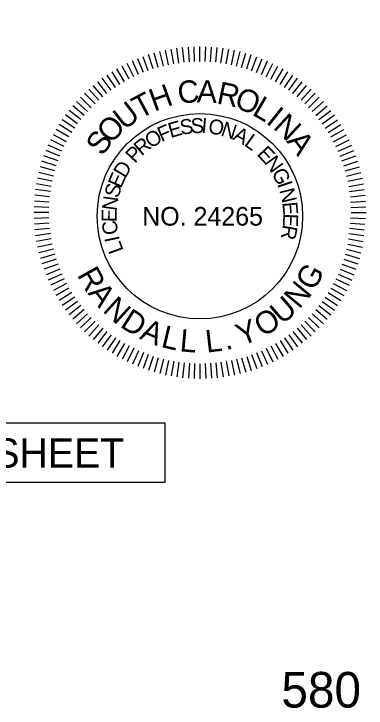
# Model space of a CAD drawing. Extents: x 1964850 to 1967424, y 1116563 to 1122204.
# Drawn here: x 1967339.7 to 1967423.6, y 1118175.5 to 1118341 of the extents above; entities that cross this region are included whole.
import ezdxf

# ---------------------------------------------------------------- set-up
doc = ezdxf.new("R2010")
doc.units = 0
for name, color, linetype in [('RD_DDB_Profile_Elev', 7, 'Continuous'), ('RD_SHT_MatchLine', 7, 'Continuous'), ('RD_Sketch1', 7, 'Continuous'), ('RD_TX_PEShield', 7, 'Continuous')]:
    doc.layers.add(name, color=color, linetype=linetype)

msp = doc.modelspace()

# ---------------------------------------------------------------- linework, layer by layer
at = {"layer": 'RD_Sketch1'}
msp.add_lwpolyline([(1967075.22, 1118243.5), (1967375.65, 1118243.5), (1967375.65, 1118229.24), (1967075.22, 1118229.24)], close=True, dxfattribs=at)
at = {"layer": 'RD_TX_PEShield'}
for p, q in [((1967375.29, 1118328.53), (1967374.43, 1118331.98)), ((1967375.29, 1118328.53), (1967374.43, 1118331.98)), ((1967376.5, 1118328.85), (1967375.76, 1118332.34)), ((1967376.5, 1118328.85), (1967375.76, 1118332.34)), ((1967377.75, 1118329.05), (1967377.13, 1118332.55)), ((1967377.75, 1118329.05), (1967377.13, 1118332.55)), ((1967378.99, 1118329.25), (1967378.49, 1118332.77)), ((1967378.99, 1118329.25), (1967378.49, 1118332.77)), ((1967380.23, 1118329.45), (1967379.86, 1118332.99)), ((1967380.23, 1118329.45), (1967379.86, 1118332.99)), ((1967381.49, 1118329.51), (1967381.24, 1118333.06)), ((1967381.49, 1118329.51), (1967381.24, 1118333.06)), ((1967382.74, 1118329.58), (1967382.62, 1118333.13)), ((1967382.74, 1118329.58), (1967382.62, 1118333.13)), ((1967384, 1118329.64), (1967384, 1118333.2)), ((1967384, 1118329.64), (1967384, 1118333.2)), ((1967385.25, 1118329.58), (1967385.38, 1118333.13)), ((1967385.25, 1118329.58), (1967385.38, 1118333.13)), ((1967386.51, 1118329.51), (1967386.76, 1118333.06)), ((1967386.51, 1118329.51), (1967386.76, 1118333.06)), ((1967387.77, 1118329.45), (1967388.14, 1118332.99)), ((1967387.77, 1118329.45), (1967388.14, 1118332.99)), ((1967389.01, 1118329.25), (1967389.5, 1118332.77)), ((1967389.01, 1118329.25), (1967389.5, 1118332.77)), ((1967390.25, 1118329.05), (1967390.87, 1118332.55)), ((1967390.25, 1118329.05), (1967390.87, 1118332.55)), ((1967391.49, 1118328.85), (1967392.23, 1118332.34)), ((1967391.49, 1118328.85), (1967392.23, 1118332.34)), ((1967391.49, 1118328.85), (1967392.23, 1118332.34)), ((1967392.71, 1118328.53), (1967393.57, 1118331.98)), ((1967392.71, 1118328.53), (1967393.57, 1118331.98)), ((1967392.71, 1118328.53), (1967393.57, 1118331.98)), ((1967370.51, 1118326.98), (1967369.18, 1118330.27)), ((1967370.51, 1118326.98), (1967369.18, 1118330.27)), ((1967371.68, 1118327.43), (1967370.47, 1118330.77)), ((1967371.68, 1118327.43), (1967370.47, 1118330.77)), ((1967372.86, 1118327.88), (1967371.76, 1118331.26)), ((1967372.86, 1118327.88), (1967371.76, 1118331.26)), ((1967374.07, 1118328.2), (1967373.09, 1118331.62)), ((1967374.07, 1118328.2), (1967373.09, 1118331.62)), ((1967393.92, 1118328.2), (1967394.9, 1118331.62)), ((1967393.92, 1118328.2), (1967394.9, 1118331.62)), ((1967393.92, 1118328.2), (1967394.9, 1118331.62)), ((1967395.14, 1118327.88), (1967396.24, 1118331.26)), ((1967395.14, 1118327.88), (1967396.24, 1118331.26)), ((1967395.14, 1118327.88), (1967396.24, 1118331.26)), ((1967396.31, 1118327.43), (1967397.53, 1118330.77)), ((1967396.31, 1118327.43), (1967397.53, 1118330.77)), ((1967396.31, 1118327.43), (1967397.53, 1118330.77)), ((1967397.48, 1118326.98), (1967398.82, 1118330.27)), ((1967397.48, 1118326.98), (1967398.82, 1118330.27)), ((1967397.48, 1118326.98), (1967398.82, 1118330.27)), ((1967367.1, 1118325.38), (1967365.43, 1118328.52)), ((1967367.1, 1118325.38), (1967365.43, 1118328.52)), ((1967368.22, 1118325.96), (1967366.66, 1118329.15)), ((1967368.22, 1118325.96), (1967366.66, 1118329.15)), ((1967369.34, 1118326.53), (1967367.89, 1118329.78)), ((1967369.34, 1118326.53), (1967367.89, 1118329.78)), ((1967398.66, 1118326.53), (1967400.11, 1118329.78)), ((1967398.66, 1118326.53), (1967400.11, 1118329.78)), ((1967398.66, 1118326.53), (1967400.11, 1118329.78)), ((1967399.78, 1118325.96), (1967401.34, 1118329.15)), ((1967399.78, 1118325.96), (1967401.34, 1118329.15)), ((1967399.78, 1118325.96), (1967401.34, 1118329.15)), ((1967400.9, 1118325.38), (1967402.57, 1118328.52)), ((1967400.9, 1118325.38), (1967402.57, 1118328.52)), ((1967400.9, 1118325.38), (1967402.57, 1118328.52)), ((1967364.92, 1118324.13), (1967363.04, 1118327.14)), ((1967364.92, 1118324.13), (1967363.04, 1118327.14)), ((1967365.98, 1118324.81), (1967364.2, 1118327.9)), ((1967365.98, 1118324.81), (1967364.2, 1118327.9)), ((1967402.02, 1118324.81), (1967403.8, 1118327.9)), ((1967402.02, 1118324.81), (1967403.8, 1118327.9)), ((1967402.02, 1118324.81), (1967403.8, 1118327.9)), ((1967403.08, 1118324.13), (1967404.96, 1118327.14)), ((1967403.08, 1118324.13), (1967404.96, 1118327.14)), ((1967403.08, 1118324.13), (1967404.96, 1118327.14)), ((1967362.81, 1118322.76), (1967360.72, 1118325.64)), ((1967362.81, 1118322.76), (1967360.72, 1118325.64)), ((1967363.87, 1118323.44), (1967361.88, 1118326.39)), ((1967363.87, 1118323.44), (1967361.88, 1118326.39)), ((1967404.13, 1118323.44), (1967406.12, 1118326.39)), ((1967404.13, 1118323.44), (1967406.12, 1118326.39)), ((1967404.13, 1118323.44), (1967406.12, 1118326.39)), ((1967405.18, 1118322.76), (1967407.28, 1118325.64)), ((1967405.18, 1118322.76), (1967407.28, 1118325.64)), ((1967405.18, 1118322.76), (1967407.28, 1118325.64)), ((1967360.86, 1118321.18), (1967358.57, 1118323.9)), ((1967360.86, 1118321.18), (1967358.57, 1118323.9)), ((1967361.83, 1118321.97), (1967359.64, 1118324.77)), ((1967361.83, 1118321.97), (1967359.64, 1118324.77)), ((1967406.16, 1118321.97), (1967408.35, 1118324.77)), ((1967406.16, 1118321.97), (1967408.35, 1118324.77)), ((1967406.16, 1118321.97), (1967408.35, 1118324.77)), ((1967407.14, 1118321.18), (1967409.42, 1118323.9)), ((1967407.14, 1118321.18), (1967409.42, 1118323.9)), ((1967407.14, 1118321.18), (1967409.42, 1118323.9)), ((1967358.99, 1118319.49), (1967356.52, 1118322.05)), ((1967358.99, 1118319.49), (1967356.52, 1118322.05)), ((1967359.88, 1118320.38), (1967357.5, 1118323.03)), ((1967359.88, 1118320.38), (1967357.5, 1118323.03)), ((1967408.12, 1118320.38), (1967410.5, 1118323.03)), ((1967408.12, 1118320.38), (1967410.5, 1118323.03)), ((1967408.12, 1118320.38), (1967410.5, 1118323.03)), ((1967409.01, 1118319.49), (1967411.48, 1118322.05)), ((1967409.01, 1118319.49), (1967411.48, 1118322.05)), ((1967409.01, 1118319.49), (1967411.48, 1118322.05)), ((1967358.1, 1118318.61), (1967355.54, 1118321.08)), ((1967358.1, 1118318.61), (1967355.54, 1118321.08)), ((1967409.89, 1118318.61), (1967412.45, 1118321.08)), ((1967409.89, 1118318.61), (1967412.45, 1118321.08)), ((1967409.89, 1118318.61), (1967412.45, 1118321.08)), ((1967356.42, 1118316.74), (1967353.7, 1118319.02)), ((1967356.42, 1118316.74), (1967353.7, 1118319.02)), ((1967357.21, 1118317.72), (1967354.57, 1118320.1)), ((1967357.21, 1118317.72), (1967354.57, 1118320.1)), ((1967410.78, 1118317.72), (1967413.43, 1118320.1)), ((1967410.78, 1118317.72), (1967413.43, 1118320.1)), ((1967410.78, 1118317.72), (1967413.43, 1118320.1)), ((1967411.58, 1118316.74), (1967414.3, 1118319.02)), ((1967411.58, 1118316.74), (1967414.3, 1118319.02)), ((1967411.58, 1118316.74), (1967414.3, 1118319.02)), ((1967354.84, 1118314.78), (1967351.96, 1118316.88)), ((1967354.84, 1118314.78), (1967351.96, 1118316.88)), ((1967355.63, 1118315.76), (1967352.83, 1118317.95)), ((1967355.63, 1118315.76), (1967352.83, 1118317.95)), ((1967412.37, 1118315.76), (1967415.17, 1118317.95)), ((1967412.37, 1118315.76), (1967415.17, 1118317.95)), ((1967412.37, 1118315.76), (1967415.17, 1118317.95)), ((1967413.16, 1118314.78), (1967416.04, 1118316.88)), ((1967413.16, 1118314.78), (1967416.04, 1118316.88)), ((1967413.16, 1118314.78), (1967416.04, 1118316.88)), ((1967354.15, 1118313.73), (1967351.2, 1118315.72)), ((1967354.15, 1118313.73), (1967351.2, 1118315.72)), ((1967413.84, 1118313.73), (1967416.79, 1118315.72)), ((1967413.84, 1118313.73), (1967416.79, 1118315.72)), ((1967413.84, 1118313.73), (1967416.79, 1118315.72)), ((1967353.47, 1118312.68), (1967350.45, 1118314.56)), ((1967353.47, 1118312.68), (1967350.45, 1118314.56)), ((1967414.53, 1118312.68), (1967417.54, 1118314.56)), ((1967414.53, 1118312.68), (1967417.54, 1118314.56)), ((1967414.53, 1118312.68), (1967417.54, 1118314.56)), ((1967352.21, 1118310.5), (1967349.07, 1118312.17)), ((1967352.21, 1118310.5), (1967349.07, 1118312.17)), ((1967352.78, 1118311.62), (1967349.7, 1118313.4)), ((1967352.78, 1118311.62), (1967349.7, 1118313.4)), ((1967415.21, 1118311.62), (1967418.3, 1118313.4)), ((1967415.21, 1118311.62), (1967418.3, 1118313.4)), ((1967415.21, 1118311.62), (1967418.3, 1118313.4)), ((1967415.78, 1118310.5), (1967418.92, 1118312.17)), ((1967415.78, 1118310.5), (1967418.92, 1118312.17)), ((1967415.78, 1118310.5), (1967418.92, 1118312.17)), ((1967351.64, 1118309.38), (1967348.44, 1118310.94)), ((1967351.64, 1118309.38), (1967348.44, 1118310.94)), ((1967416.36, 1118309.38), (1967419.55, 1118310.94)), ((1967416.36, 1118309.38), (1967419.55, 1118310.94)), ((1967416.36, 1118309.38), (1967419.55, 1118310.94)), ((1967351.07, 1118308.26), (1967347.82, 1118309.71)), ((1967351.07, 1118308.26), (1967347.82, 1118309.71)), ((1967416.93, 1118308.26), (1967420.18, 1118309.71)), ((1967416.93, 1118308.26), (1967420.18, 1118309.71)), ((1967416.93, 1118308.26), (1967420.18, 1118309.71)), ((1967350.17, 1118305.91), (1967346.83, 1118307.13)), ((1967350.17, 1118305.91), (1967346.83, 1118307.13)), ((1967350.62, 1118307.08), (1967347.32, 1118308.42)), ((1967350.62, 1118307.08), (1967347.32, 1118308.42)), ((1967417.38, 1118307.08), (1967420.67, 1118308.42)), ((1967417.38, 1118307.08), (1967420.67, 1118308.42)), ((1967417.38, 1118307.08), (1967420.67, 1118308.42)), ((1967417.83, 1118305.91), (1967421.17, 1118307.13)), ((1967417.83, 1118305.91), (1967421.17, 1118307.13)), ((1967417.83, 1118305.91), (1967421.17, 1118307.13)), ((1967349.72, 1118304.74), (1967346.33, 1118305.84)), ((1967349.72, 1118304.74), (1967346.33, 1118305.84)), ((1967418.28, 1118304.74), (1967421.66, 1118305.84)), ((1967418.28, 1118304.74), (1967421.66, 1118305.84)), ((1967418.28, 1118304.74), (1967421.66, 1118305.84)), ((1967349.39, 1118303.52), (1967345.97, 1118304.5)), ((1967349.39, 1118303.52), (1967345.97, 1118304.5)), ((1967418.6, 1118303.52), (1967422.02, 1118304.5)), ((1967418.6, 1118303.52), (1967422.02, 1118304.5)), ((1967418.6, 1118303.52), (1967422.02, 1118304.5)), ((1967349.07, 1118302.31), (1967345.62, 1118303.17)), ((1967349.07, 1118302.31), (1967345.62, 1118303.17)), ((1967418.93, 1118302.31), (1967422.38, 1118303.17)), ((1967418.93, 1118302.31), (1967422.38, 1118303.17)), ((1967418.93, 1118302.31), (1967422.38, 1118303.17)), ((1967348.54, 1118299.85), (1967345.04, 1118300.47)), ((1967348.54, 1118299.85), (1967345.04, 1118300.47)), ((1967348.74, 1118301.09), (1967345.26, 1118301.83)), ((1967348.74, 1118301.09), (1967345.26, 1118301.83)), ((1967419.25, 1118301.09), (1967422.74, 1118301.83)), ((1967419.25, 1118301.09), (1967422.74, 1118301.83)), ((1967419.25, 1118301.09), (1967422.74, 1118301.83)), ((1967419.45, 1118299.85), (1967422.95, 1118300.47)), ((1967419.45, 1118299.85), (1967422.95, 1118300.47)), ((1967419.45, 1118299.85), (1967422.95, 1118300.47)), ((1967348.35, 1118298.61), (1967344.83, 1118299.1)), ((1967348.35, 1118298.61), (1967344.83, 1118299.1)), ((1967419.65, 1118298.61), (1967423.17, 1118299.1)), ((1967419.65, 1118298.61), (1967423.17, 1118299.1)), ((1967419.65, 1118298.61), (1967423.17, 1118299.1)), ((1967348.15, 1118297.37), (1967344.61, 1118297.74)), ((1967348.15, 1118297.37), (1967344.61, 1118297.74)), ((1967419.85, 1118297.37), (1967423.39, 1118297.74)), ((1967419.85, 1118297.37), (1967423.39, 1118297.74)), ((1967419.85, 1118297.37), (1967423.39, 1118297.74)), ((1967348.08, 1118296.11), (1967344.54, 1118296.36)), ((1967348.08, 1118296.11), (1967344.54, 1118296.36)), ((1967419.91, 1118296.11), (1967423.46, 1118296.36)), ((1967419.91, 1118296.11), (1967423.46, 1118296.36)), ((1967419.91, 1118296.11), (1967423.46, 1118296.36)), ((1967348.02, 1118294.85), (1967344.46, 1118294.98)), ((1967348.02, 1118294.85), (1967344.46, 1118294.98)), ((1967419.98, 1118294.85), (1967423.53, 1118294.98)), ((1967419.98, 1118294.85), (1967423.53, 1118294.98)), ((1967419.98, 1118294.85), (1967423.53, 1118294.98)), ((1967347.95, 1118293.6), (1967344.39, 1118293.6)), ((1967347.95, 1118293.6), (1967344.39, 1118293.6)), ((1967348.02, 1118292.34), (1967344.46, 1118292.22)), ((1967348.02, 1118292.34), (1967344.46, 1118292.22)), ((1967419.91, 1118292.34), (1967423.46, 1118292.22)), ((1967419.91, 1118292.34), (1967423.46, 1118292.22)), ((1967420.04, 1118293.6), (1967423.6, 1118293.6)), ((1967420.04, 1118293.6), (1967423.6, 1118293.6)), ((1967420.04, 1118293.6), (1967423.6, 1118293.6)), ((1967348.08, 1118291.09), (1967344.54, 1118290.84)), ((1967348.08, 1118291.09), (1967344.54, 1118290.84)), ((1967419.78, 1118291.1), (1967423.31, 1118290.85)), ((1967419.78, 1118291.1), (1967423.31, 1118290.85)), ((1967348.15, 1118289.83), (1967344.61, 1118289.46)), ((1967348.15, 1118289.83), (1967344.61, 1118289.46)), ((1967419.65, 1118289.85), (1967423.17, 1118289.48)), ((1967419.65, 1118289.85), (1967423.17, 1118289.48)), ((1967348.35, 1118288.59), (1967344.83, 1118288.09)), ((1967348.35, 1118288.59), (1967344.83, 1118288.09)), ((1967348.54, 1118287.35), (1967345.04, 1118286.73)), ((1967348.54, 1118287.35), (1967345.04, 1118286.73)), ((1967419.39, 1118287.36), (1967422.88, 1118286.74)), ((1967419.39, 1118287.36), (1967422.88, 1118286.74)), ((1967419.52, 1118288.61), (1967423.03, 1118288.11)), ((1967419.52, 1118288.61), (1967423.03, 1118288.11)), ((1967348.74, 1118286.1), (1967345.26, 1118285.36)), ((1967348.74, 1118286.1), (1967345.26, 1118285.36)), ((1967419.25, 1118286.1), (1967422.74, 1118285.36)), ((1967419.25, 1118286.1), (1967422.74, 1118285.36)), ((1967349.07, 1118284.89), (1967345.62, 1118284.03)), ((1967349.07, 1118284.89), (1967345.62, 1118284.03)), ((1967418.93, 1118284.89), (1967422.38, 1118284.03)), ((1967418.93, 1118284.89), (1967422.38, 1118284.03)), ((1967349.39, 1118283.67), (1967345.97, 1118282.69)), ((1967349.39, 1118283.67), (1967345.97, 1118282.69)), ((1967349.72, 1118282.46), (1967346.33, 1118281.36)), ((1967418.28, 1118282.46), (1967421.66, 1118281.36)), ((1967418.28, 1118282.46), (1967421.66, 1118281.36)), ((1967418.6, 1118283.67), (1967422.02, 1118282.69)), ((1967418.6, 1118283.67), (1967422.02, 1118282.69)), ((1967350.17, 1118281.28), (1967346.83, 1118280.07)), ((1967350.17, 1118281.28), (1967346.83, 1118280.07)), ((1967417.83, 1118281.28), (1967421.17, 1118280.07)), ((1967417.83, 1118281.28), (1967421.17, 1118280.07)), ((1967350.62, 1118280.11), (1967347.32, 1118278.78)), ((1967350.62, 1118280.11), (1967347.32, 1118278.78)), ((1967351.07, 1118278.94), (1967347.82, 1118277.49)), ((1967351.07, 1118278.94), (1967347.82, 1118277.49)), ((1967416.93, 1118278.94), (1967420.18, 1118277.49)), ((1967416.93, 1118278.94), (1967420.18, 1118277.49)), ((1967417.38, 1118280.11), (1967420.67, 1118278.78)), ((1967417.38, 1118280.11), (1967420.67, 1118278.78)), ((1967351.64, 1118277.82), (1967348.44, 1118276.26)), ((1967351.64, 1118277.82), (1967348.44, 1118276.26)), ((1967416.36, 1118277.82), (1967419.55, 1118276.26)), ((1967416.36, 1118277.82), (1967419.55, 1118276.26)), ((1967352.21, 1118276.7), (1967349.07, 1118275.03)), ((1967352.21, 1118276.7), (1967349.07, 1118275.03)), ((1967352.78, 1118275.58), (1967349.7, 1118273.8)), ((1967352.78, 1118275.58), (1967349.7, 1118273.8)), ((1967415.21, 1118275.58), (1967418.3, 1118273.8)), ((1967415.21, 1118275.58), (1967418.3, 1118273.8)), ((1967415.78, 1118276.7), (1967418.92, 1118275.03)), ((1967415.78, 1118276.7), (1967418.92, 1118275.03)), ((1967353.47, 1118274.52), (1967350.45, 1118272.64)), ((1967353.47, 1118274.52), (1967350.45, 1118272.64)), ((1967414.53, 1118274.52), (1967417.54, 1118272.64)), ((1967414.53, 1118274.52), (1967417.54, 1118272.64)), ((1967354.15, 1118273.47), (1967351.2, 1118271.48)), ((1967354.15, 1118273.47), (1967351.2, 1118271.48)), ((1967354.84, 1118272.41), (1967351.96, 1118270.32)), ((1967354.84, 1118272.41), (1967351.96, 1118270.32)), ((1967413.16, 1118272.41), (1967416.04, 1118270.32)), ((1967413.16, 1118272.41), (1967416.04, 1118270.32)), ((1967413.84, 1118273.47), (1967416.79, 1118271.48)), ((1967413.84, 1118273.47), (1967416.79, 1118271.48)), ((1967355.63, 1118271.43), (1967352.83, 1118269.24)), ((1967355.63, 1118271.43), (1967352.83, 1118269.24)), ((1967412.37, 1118271.43), (1967415.17, 1118269.24)), ((1967412.37, 1118271.43), (1967415.17, 1118269.24)), ((1967356.42, 1118270.46), (1967353.7, 1118268.17)), ((1967356.42, 1118270.46), (1967353.7, 1118268.17)), ((1967357.21, 1118269.48), (1967354.57, 1118267.1)), ((1967357.21, 1118269.48), (1967354.57, 1118267.1)), ((1967410.78, 1118269.48), (1967413.43, 1118267.1)), ((1967410.78, 1118269.48), (1967413.43, 1118267.1)), ((1967411.58, 1118270.46), (1967414.3, 1118268.17)), ((1967411.58, 1118270.46), (1967414.3, 1118268.17)), ((1967358.1, 1118268.59), (1967355.54, 1118266.12)), ((1967358.1, 1118268.59), (1967355.54, 1118266.12)), ((1967358.99, 1118267.7), (1967356.52, 1118265.14)), ((1967358.99, 1118267.7), (1967356.52, 1118265.14)), ((1967409.01, 1118267.7), (1967411.48, 1118265.14)), ((1967409.01, 1118267.7), (1967411.48, 1118265.14)), ((1967409.89, 1118268.59), (1967412.45, 1118266.12)), ((1967409.89, 1118268.59), (1967412.45, 1118266.12)), ((1967359.88, 1118266.81), (1967357.5, 1118264.17)), ((1967359.88, 1118266.81), (1967357.5, 1118264.17)), ((1967360.86, 1118266.02), (1967358.57, 1118263.3)), ((1967360.86, 1118266.02), (1967358.57, 1118263.3)), ((1967407.14, 1118266.02), (1967409.42, 1118263.3)), ((1967407.14, 1118266.02), (1967409.42, 1118263.3)), ((1967408.12, 1118266.81), (1967410.5, 1118264.17)), ((1967361.83, 1118265.23), (1967359.64, 1118262.43)), ((1967361.83, 1118265.23), (1967359.64, 1118262.43)), ((1967362.81, 1118264.44), (1967360.72, 1118261.56)), ((1967362.81, 1118264.44), (1967360.72, 1118261.56)), ((1967405.18, 1118264.44), (1967407.28, 1118261.56)), ((1967405.18, 1118264.44), (1967407.28, 1118261.56)), ((1967406.16, 1118265.23), (1967408.35, 1118262.43)), ((1967406.16, 1118265.23), (1967408.35, 1118262.43)), ((1967363.87, 1118263.75), (1967361.88, 1118260.8)), ((1967363.87, 1118263.75), (1967361.88, 1118260.8)), ((1967364.92, 1118263.07), (1967363.04, 1118260.05)), ((1967364.92, 1118263.07), (1967363.04, 1118260.05)), ((1967365.98, 1118262.38), (1967364.2, 1118259.3)), ((1967365.98, 1118262.38), (1967364.2, 1118259.3)), ((1967402.02, 1118262.38), (1967403.8, 1118259.3)), ((1967402.02, 1118262.38), (1967403.8, 1118259.3)), ((1967403.08, 1118263.07), (1967404.96, 1118260.05)), ((1967403.08, 1118263.07), (1967404.96, 1118260.05)), ((1967404.13, 1118263.75), (1967406.12, 1118260.8)), ((1967404.13, 1118263.75), (1967406.12, 1118260.8)), ((1967367.1, 1118261.81), (1967365.43, 1118258.67)), ((1967367.1, 1118261.81), (1967365.43, 1118258.67)), ((1967368.22, 1118261.24), (1967366.66, 1118258.04)), ((1967368.22, 1118261.24), (1967366.66, 1118258.04)), ((1967369.34, 1118260.67), (1967367.89, 1118257.42)), ((1967369.34, 1118260.67), (1967367.89, 1118257.42)), ((1967398.66, 1118260.67), (1967400.11, 1118257.42)), ((1967398.66, 1118260.67), (1967400.11, 1118257.42)), ((1967399.78, 1118261.24), (1967401.34, 1118258.04)), ((1967399.78, 1118261.24), (1967401.34, 1118258.04)), ((1967400.9, 1118261.81), (1967402.57, 1118258.67)), ((1967400.9, 1118261.81), (1967402.57, 1118258.67)), ((1967370.51, 1118260.22), (1967369.18, 1118256.92)), ((1967370.51, 1118260.22), (1967369.18, 1118256.92)), ((1967371.68, 1118259.77), (1967370.47, 1118256.43)), ((1967371.68, 1118259.77), (1967370.47, 1118256.43)), ((1967372.86, 1118259.32), (1967371.76, 1118255.93)), ((1967372.86, 1118259.32), (1967371.76, 1118255.93)), ((1967374.07, 1118258.99), (1967373.09, 1118255.57)), ((1967374.07, 1118258.99), (1967373.09, 1118255.57)), ((1967393.92, 1118258.99), (1967394.9, 1118255.57)), ((1967393.92, 1118258.99), (1967394.9, 1118255.57)), ((1967395.14, 1118259.32), (1967396.24, 1118255.93)), ((1967395.14, 1118259.32), (1967396.24, 1118255.93)), ((1967396.31, 1118259.77), (1967397.53, 1118256.43)), ((1967396.31, 1118259.77), (1967397.53, 1118256.43)), ((1967397.48, 1118260.22), (1967398.82, 1118256.92)), ((1967397.48, 1118260.22), (1967398.82, 1118256.92)), ((1967375.29, 1118258.67), (1967374.43, 1118255.22)), ((1967375.29, 1118258.67), (1967374.43, 1118255.22)), ((1967376.5, 1118258.34), (1967375.76, 1118254.86)), ((1967376.5, 1118258.34), (1967375.76, 1118254.86)), ((1967377.75, 1118258.14), (1967377.13, 1118254.64)), ((1967377.75, 1118258.14), (1967377.13, 1118254.64)), ((1967378.99, 1118257.95), (1967378.49, 1118254.43)), ((1967378.99, 1118257.95), (1967378.49, 1118254.43)), ((1967380.23, 1118257.75), (1967379.86, 1118254.21)), ((1967380.23, 1118257.75), (1967379.86, 1118254.21)), ((1967381.49, 1118257.68), (1967381.24, 1118254.14)), ((1967381.49, 1118257.68), (1967381.24, 1118254.14)), ((1967382.74, 1118257.62), (1967382.62, 1118254.06)), ((1967382.74, 1118257.62), (1967382.62, 1118254.06)), ((1967384, 1118257.55), (1967384, 1118253.99)), ((1967384, 1118257.55), (1967384, 1118253.99)), ((1967385.25, 1118257.62), (1967385.38, 1118254.06)), ((1967385.25, 1118257.62), (1967385.38, 1118254.06)), ((1967386.51, 1118257.68), (1967386.76, 1118254.14)), ((1967386.51, 1118257.68), (1967386.76, 1118254.14)), ((1967387.77, 1118257.75), (1967388.14, 1118254.21)), ((1967387.77, 1118257.75), (1967388.14, 1118254.21)), ((1967389.01, 1118257.95), (1967389.5, 1118254.43)), ((1967389.01, 1118257.95), (1967389.5, 1118254.43)), ((1967390.25, 1118258.14), (1967390.87, 1118254.64)), ((1967390.25, 1118258.14), (1967390.87, 1118254.64)), ((1967391.49, 1118258.34), (1967392.23, 1118254.86)), ((1967391.49, 1118258.34), (1967392.23, 1118254.86)), ((1967392.71, 1118258.67), (1967393.57, 1118255.22)), ((1967392.71, 1118258.67), (1967393.57, 1118255.22))]:
    msp.add_line(p, q, dxfattribs=at)
msp.add_circle((1967384, 1118292.72), 24.48, dxfattribs=at)

# ---------------------------------------------------------------- texts
at = {"layer": 'RD_DDB_Profile_Elev'}
msp.add_text('580', height=8.5, dxfattribs=at).set_placement((1967403.42, 1118175.58))
at = {"layer": 'RD_SHT_MatchLine'}
msp.add_text('Match Line Sta. 70+00.00 (See Sheet No. 8)', height=8, rotation=77.0152, dxfattribs=at).set_placement((1967301.59, 1118288.26))
at = {"layer": 'RD_Sketch1'}
msp.add_text('ALIGNMENT CONTROL CAN BE FOUND ON REFERENCE SHEET', height=7, dxfattribs=at).set_placement((1967078.87, 1118232.79))
at = {"layer": 'RD_TX_PEShield'}
for s, height, rotation, p in [('C', 5.34, 6.8832, (1967378.99, 1118319.46)), ('A', 5.34, 357.9448, (1967383.21, 1118319.91)), ('H', 5.34, 19.9102, (1967373.09, 1118317.64)), ('R', 5.34, 348.267, (1967387.79, 1118319.66)), ('T', 5.34, 28.0947, (1967369.66, 1118315.83)), ('O', 5.34, 339.3286, (1967391.93, 1118318.74)), ('L', 5.34, 329.6507, (1967396.19, 1118317.04)), ('U', 5.34, 37.7726, (1967365.98, 1118313.09)), ('I', 5.34, 321.4663, (1967399.53, 1118315.05)), ('N', 5.34, 317.0007, (1967401.22, 1118313.78)), ('O', 5.34, 47.4504, (1967362.81, 1118309.78)), ('E', 3.56, 16.1843, (1967377, 1118311.35)), ('S', 3.56, 8.6909, (1967379.49, 1118312.11)), ('S', 3.56, 1.79, (1967381.85, 1118312.51)), ('I', 3.56, 354.889, (1967384.24, 1118312.62)), ('O', 3.56, 350.4045, (1967385.8, 1118312.54)), ('N', 3.56, 341.7029, (1967388.78, 1118312.04)), ('F', 3.56, 23.0853, (1967374.81, 1118310.38)), ('A', 3.56, 333.0013, (1967391.64, 1118311.1)), ('S', 5.34, 54.9027, (1967360.77, 1118306.88)), ('O', 3.56, 31.7869, (1967372.24, 1118308.78)), ('L', 3.56, 324.2997, (1967394.34, 1118309.73)), ('A', 5.34, 307.3229, (1967404.51, 1118310.58)), ('R', 3.56, 39.8902, (1967370.09, 1118306.97)), ('P', 3.56, 46.7912, (1967368.48, 1118305.19)), ('E', 3.56, 313.2251, (1967397.41, 1118307.43)), ('N', 3.56, 305.7317, (1967399.21, 1118305.55)), ('D', 3.56, 59.074, (1967366.19, 1118301.61)), ('G', 3.56, 297.0301, (1967400.98, 1118303.1)), ('E', 3.56, 66.5674, (1967365.18, 1118299.21)), ('S', 3.56, 73.4683, (1967364.54, 1118296.9)), ('I', 3.56, 288.3285, (1967402.36, 1118300.41)), ('N', 3.56, 283.8441, (1967402.9, 1118298.95)), ('N', 3.56, 82.17, (1967364.13, 1118293.91)), ('E', 3.56, 275.1424, (1967403.63, 1118296.02)), ('E', 3.56, 89.6633, (1967364.14, 1118291.31)), ('E', 3.56, 267.6491, (1967403.89, 1118293.43)), ('C', 3.56, 97.7667, (1967364.54, 1118288.52)), ('R', 3.56, 260.1557, (1967403.81, 1118290.83)), ('I', 3.56, 102.2511, (1967364.93, 1118287.01)), ('L', 3.56, 109.7445, (1967365.83, 1118284.57)), ('R', 5.34, 299.1493, (1967354.6, 1118278.75)), ('G', 5.34, 60.1113, (1967411.11, 1118274.7)), ('N', 5.34, 50.4335, (1967407.69, 1118270.4)), ('A', 5.34, 308.0877, (1967357.12, 1118274.35)), ('N', 5.34, 317.7655, (1967360.59, 1118270.09)), ('U', 5.34, 40.7556, (1967403.6, 1118266.73)), ('D', 5.34, 327.4433, (1967364.73, 1118266.48)), ('O', 5.34, 31.0778, (1967398.95, 1118263.8)), ('A', 5.34, 337.1212, (1967369.42, 1118263.61)), ('Y', 5.34, 21.4, (1967393.88, 1118261.7)), ('L', 5.34, 346.799, (1967374.52, 1118261.58)), ('L', 5.34, 354.9835, (1967379.05, 1118260.54)), ('L', 5.34, 6.5171, (1967385.58, 1118260.2)), ('.', 5.34, 14.7016, (1967390.19, 1118260.76))]:
    msp.add_text(s, height=height, rotation=rotation, dxfattribs=at).set_placement(p)
msp.add_text('NO. 24265', height=4.45, dxfattribs=at).set_placement((1967370.24, 1118290.49))

doc.saveas('drawing.dxf')
